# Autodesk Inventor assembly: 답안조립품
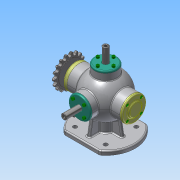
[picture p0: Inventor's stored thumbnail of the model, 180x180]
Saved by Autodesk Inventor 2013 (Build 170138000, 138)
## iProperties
Created: 2016-03
Part Number: 답안조립품
Document SubType Name: Assembly
Designer: Administrator
Mass: 3007.62 g
Surface Area: 2215.43 cm^2
Volume: 827.087 cm^3
Density: 3.6364 g/cm^3
Author: Administrator
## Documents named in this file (17)
- C:\Users\Administrator\Desktop\360308V1029\답안조립품.iam
- C:\Users\Administrator\Desktop\360308V1029\본체.ipt
- C:\Users\Administrator\Desktop\360308V1029\너트-M8x1.ipt
- C:\Users\Administrator\Desktop\360308V1029\뒤커버.ipt
- C:\Users\Administrator\Desktop\360308V1029\베어링- 6202.ipt
- C:\Users\Administrator\Desktop\360308V1029\본체커버.ipt
- C:\Users\Administrator\Desktop\360308V1029\볼트 M4x0.7.ipt
- C:\Users\Administrator\Desktop\360308V1029\스프로킷.ipt
- C:\Users\Administrator\Desktop\360308V1029\슬라이드 커버.ipt
- C:\Users\Administrator\Desktop\360308V1029\슬라이드.ipt
- C:\Users\Administrator\Desktop\360308V1029\앞커버.ipt
- C:\Users\Administrator\Desktop\360308V1029\오일실.ipt
- C:\Users\Administrator\Desktop\360308V1029\와셔 8x17.ipt
- C:\Users\Administrator\Desktop\360308V1029\축.ipt
- C:\Users\Administrator\Desktop\360308V1029\키 3 x 3 x 12.ipt
- C:\Users\Administrator\Desktop\360308V1029\스프링 1.ipt
- C:\Users\Administrator\Desktop\360308V1029\스프링 2.ipt
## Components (17 placed, 1 different names)
1. M4x0.7x12:17
2. M4x0.7x12:1
3. M4x0.7x12:5
4. M4x0.7x12:6
5. M4x0.7x12:7
6. M4x0.7x12:4
7. M4x0.7x12:8
8. M4x0.7x12:9
9. M4x0.7x12:10
10. M4x0.7x12:2
11. M4x0.7x12:11
12. M4x0.7x12:12
13. M4x0.7x12:13
14. M4x0.7x12:3
15. M4x0.7x12:14
16. M4x0.7x12:15
17. M4x0.7x12:16
